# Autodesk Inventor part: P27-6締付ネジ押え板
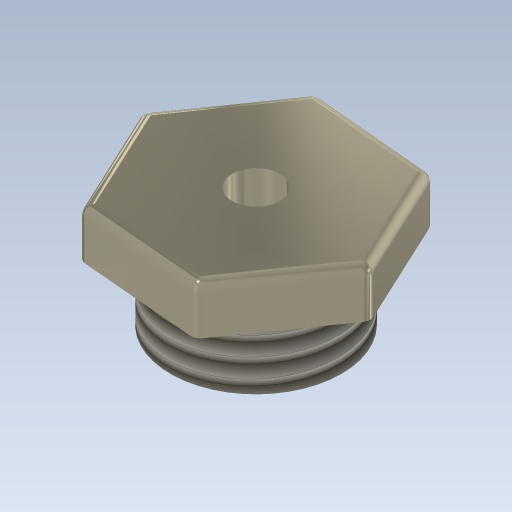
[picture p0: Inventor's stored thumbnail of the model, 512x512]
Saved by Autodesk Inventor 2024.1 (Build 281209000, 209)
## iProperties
Shininess: 64.0
Length Units: 11269
Angle Units: 11279
Time Units: 11290
Mass Units: 11284
Length Display Precision: 2
Angle Display Precision: 1
Created: 2002-10
Part Number: P27-6締付ネジ押え板
Document SubType Name: ﾓﾃﾞﾘﾝｸﾞ
Designer: 株式会社富士システム
Stock Number: P24-6締付ネジ押え板
Density: 1 g/cm^3
Material: 一般
Appearance: ニッケル
Density: 0.0
Volumn: 0.0
Area: 0.0
PropertySet Name: Model Information
Control State: 0
Master: False
Checked Out: False
Author: 株式会社富士システム
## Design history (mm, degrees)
sketch "ｽｹｯﾁ1"
  geometry: C1 r 18 at (16.993, -14.869)
  constraints: 1 centre point
  dimensions: "d0" = 36 diameter of C1
extrude "押し出し1" new body sketch "ｽｹｯﾁ1" distance "d1" = 15; taper "d2" = 0 deg
sketch "ｽｹｯﾁ2"
  geometry: L1 (11.232, -24.066)-(-15.225, -21.76); L2 (-15.225, -21.76)-(-26.458, 2.305); L3 (-26.458, 2.305)-(-11.232, 24.066); L4 (-11.232, 24.066)-(15.225, 21.76); L5 (15.225, 21.76)-(26.458, -2.305); L6 (26.458, -2.305)-(11.232, -24.066); C1 r 18 at (0, 0) reference; 1 further point
  constraints: 12 end point, 1 coincident, 11 other
  dimensions: "d4" = 23 distance from line of L4 L5.end
extrude "押し出し2" join sketch "ｽｹｯﾁ2" distance "d5" = 10; taper "d6" = 0 deg
feature "ねじ1" dims "d7" = 10, "d8" = 0
sketch "ｽｹｯﾁ3"
  geometry: C1 r 18 at (0, 0) reference; C2 r 5 at (0, 0)
  constraints: 1 centre point, 1 coincident
  dimensions: "d9" = 10 diameter of C2
extrude "押し出し3" cut sketch "ｽｹｯﾁ3" extent not by distance; stored distance "d10" = 10; taper "d11" = 0 deg
fillet "ﾌｨﾚｯﾄ1" dims "d12" = 2
node "ソリッド1"
node "ソリッド ボディ"
node "サーフェス ボディ"
